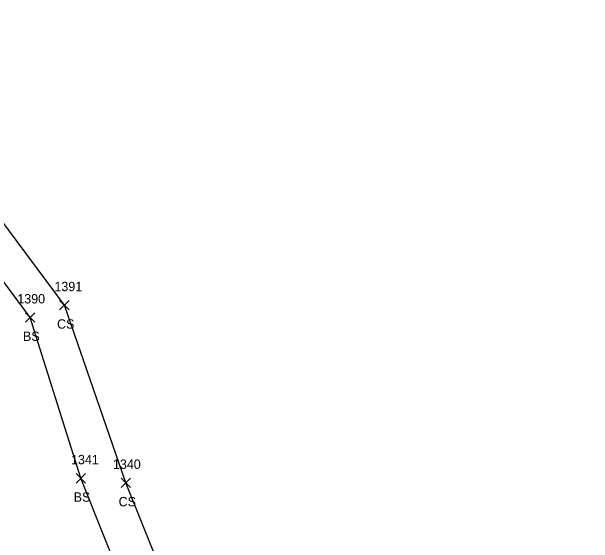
# Model space of a CAD drawing. Extents: x 1415642 to 1422021, y 544543 to 547232.
# Drawn here: x 1416364 to 1416488.3, y 546735.7 to 546849.3 of the extents above; entities that cross this region are included whole.
import ezdxf

# ---------------------------------------------------------------- set-up
doc = ezdxf.new("R2010")
doc.units = 0
for name, color, linetype in [('L_A', 7, 'Continuous'), ('L_I', 7, 'Continuous'), ('L_TIC', 7, 'Continuous'), ('LELB', 7, 'Continuous')]:
    doc.layers.add(name, color=color, linetype=linetype)

msp = doc.modelspace()

# ---------------------------------------------------------------- linework, layer by layer
at = {"layer": 'L_TIC'}
for points in [[(1416374.25, 546785.59), (1416376.25, 546787.59)], [(1416376.25, 546785.59), (1416374.25, 546787.59)], [(1416366.97, 546782.97), (1416368.97, 546784.97)], [(1416368.97, 546782.97), (1416366.97, 546784.97)], [(1416377.8, 546748.63), (1416379.8, 546750.63)], [(1416379.8, 546748.63), (1416377.8, 546750.63)], [(1416387.41, 546747.65), (1416389.41, 546749.65)], [(1416389.41, 546747.65), (1416387.41, 546749.65)]]:
    msp.add_lwpolyline(points, dxfattribs=at)
at = {"layer": 'LELB'}
for points in [[(1416488.29, 546504.83), (1416488.12, 546506.46), (1416480.5, 546522.11), (1416462.74, 546551.59), (1416447.84, 546594.51), (1416422.44, 546641.16), (1416410.18, 546676.27), (1416393.07, 546713.79), (1416378.8, 546749.63), (1416367.97, 546783.97), (1416347.35, 546811.63), (1416340.26, 546839.45), (1416338.76, 546849.28)], [(1416488.29, 546504.83), (1416488.12, 546506.46), (1416480.5, 546522.11), (1416462.74, 546551.59), (1416447.84, 546594.51), (1416422.44, 546641.16), (1416410.17, 546676.27), (1416393.07, 546713.79), (1416378.8, 546749.63), (1416367.97, 546783.97), (1416347.34, 546811.63), (1416340.26, 546839.45), (1416338.76, 546849.28)], [(1416449.42, 546597.09), (1416431.29, 546645.7), (1416419.63, 546678.87), (1416400.37, 546718.89), (1416388.41, 546748.65), (1416375.25, 546786.59), (1416353.32, 546816.02), (1416347.15, 546837.59)], [(1416449.42, 546597.08), (1416431.29, 546645.7), (1416419.63, 546678.87), (1416400.37, 546718.89), (1416388.42, 546748.65), (1416375.25, 546786.59), (1416353.33, 546816.03), (1416347.15, 546837.59)]]:
    msp.add_lwpolyline(points, dxfattribs=at)

# ---------------------------------------------------------------- texts
at = {"layer": 'L_A'}
for s, p in [('CS', (1416373.69, 546781.59)), ('BS', (1416366.41, 546778.97)), ('BS', (1416377.24, 546744.63)), ('CS', (1416386.85, 546743.65))]:
    msp.add_text(s, height=2, dxfattribs=at).set_placement(p)
at = {"layer": 'L_I'}
for s, p in [('1391', (1416373.13, 546789.59)), ('1390', (1416365.19, 546786.97)), ('1341', (1416376.67, 546752.63)), ('1340', (1416385.63, 546751.65))]:
    msp.add_text(s, height=2, dxfattribs=at).set_placement(p)

doc.saveas('drawing.dxf')
